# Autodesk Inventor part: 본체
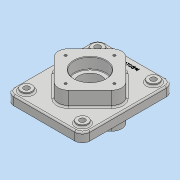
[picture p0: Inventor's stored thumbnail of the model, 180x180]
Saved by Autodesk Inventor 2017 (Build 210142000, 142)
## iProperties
Part Number: 본체
Material: 일반
Document SubType Name: Modeling
Designer: MRC
Density: 1 g/cm^3
Appearance: 기본값
Author: MRC
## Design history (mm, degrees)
sketch "스케치1"
  geometry: L1 (-75, -90)-(75, -90); L2 (75, -90)-(75, 90); L3 (75, 90)-(-75, 90); L4 (-75, 90)-(-75, -90); L5 (-75, -90)-(75, 90); L6 (75, -90)-(-75, 90); 1 further point
  constraints: 12 end point, 2 midpoint, 2 parallel, 1 horizontal, 1 perpendicular
  dimensions: "d0" = 150 distance of L2.end L3.end; "d1" = 180 distance of L3.end L1.start
extrude "돌출1" new body sketch "스케치1" distance "d2" = 18; taper "d3" = 0 deg
sketch "스케치2"
  geometry: L1 (0, -70.711)-(70.711, 0); L2 (70.711, 0)-(0, 70.711); L3 (0, 70.711)-(-70.711, 0); L4 (-70.711, 0)-(0, -70.711); L5 (0, -70.711)-(0, 70.711); L6 (70.711, 0)-(-70.711, 0); 1 further point
  constraints: 12 end point, 2 midpoint, 2 parallel, 1 horizontal, 1 perpendicular, 1 vertical
  dimensions: "d4" = 100 distance of L3.end L1.start
extrude "돌출2" join sketch "스케치2" distance "d5" = 29; taper "d6" = 0 deg
sketch "스케치3"
  geometry: L1 (0, -70.711)-(-70.711, 0) reference; L2 (-70.711, 0)-(0, 70.711) reference; L3 (0, 70.711)-(70.711, 0) reference; L4 (70.711, 0)-(0, -70.711) reference; 1 further point
extrude "돌출3" join sketch "스케치3" distance "d7" = 23; taper "d8" = 0 deg
fillet "모깎기1" dims "d9" = 15
sketch "스케치4"
  geometry: L1 (-75, 75)-(-75, -75) reference; L2 (-60, -90)-(60, -90) reference; L3 (75, -75)-(75, 75) reference; L4 (60, 90)-(-60, 90) reference; L5 (0, -70.711)-(-70.711, 0) reference; L6 (-70.711, 0)-(0, 70.711) reference; L7 (0, 70.711)-(70.711, 0) reference; L8 (70.711, 0)-(0, -70.711) reference; A1 r 15 centre (-60, 75) between (-60, 90) and (-75, 75) reference; A2 r 15 centre (-60, -75) between (-75, -75) and (-60, -90) reference; A3 r 15 centre (60, -75) between (60, -90) and (75, -75) reference; A4 r 15 centre (60, 75) between (75, 75) and (60, 90) reference; 2 further points
  constraints: 1 vertical alignment, 1 other
  dimensions: "d10" = 15 distance from line of L4 point (0, 75)
feature "엠보싱1" sketch "스케치4" dims "d0" = 150, "d1" = 180, "d11" = 0.5, "d12" = 0
fillet "모깎기2" dims "d13" = 20
sketch "스케치5"
  geometry: 1 further point
hole "구멍1" sketch "스케치5" at (0, 0) diameter "d14" = 45; stored, may be unused: countersink angle "d18" = 90 deg, drill point angle "d20" = 0 deg; dims "d15" = 6, "d16" = 62, "d17" = 22, "d19" = 100
sketch "스케치6"
  geometry: C1 r 31 at (0, 0); 1 further point
  constraints: 1 centre point, 1 coincident
  dimensions: "d21" = 62 diameter of C1
extrude "돌출4" cut sketch "스케치6" distance "d22" = 22; taper "d23" = 0 deg
sketch "스케치7"
  geometry: C1 r 11 at (-55, -70); 1 further point
  constraints: 1 centre point
  dimensions: "d24" = 22 diameter of C1; "d25" = 55 horizontal distance of point (0, 0) C1.centre; "d26" = 70 vertical distance of point (0, 0) C1.centre
extrude "돌출5" join sketch "스케치7" distance "d27" = 5; taper "d28" = 0 deg
sketch "스케치8"
  geometry: C1 r 5.5 at (0, 0); C2 r 11 at (0, 0) reference; 1 further point
  constraints: 1 centre point, 1 concentric
  dimensions: "d29" = 11 diameter of C1
extrude "돌출6" cut sketch "스케치8" stored distance "d30" = 5; taper "d31" = 0 deg
sketch "스케치9"
  geometry: 2 further points
  constraints: 1 vertical alignment
  dimensions: "d38" = 48 distance of point (0, 48) point (0, 0)
hole "구멍2" sketch "스케치9" at (0, 48) diameter "d39" = 4.917; stored, may be unused: countersink angle "d43" = 90 deg, drill point angle "d45" = 118 deg; dims "d40" = 10, "d41" = 62, "d42" = 22, "d44" = 13
node "작업 평면1"
fillet "모깎기3" dims "d49" = 3
fillet "모깎기4" dims "d50" = 1
chamfer "모따기1" distance "d51" = 1; stored, may be unused: second distance "d52" = 2, angle "d53" = 45 deg
node "솔리드1"
pattern_linear "직사각형 패턴1" dims "d34" = 110, "d37" = 140
pattern_circular "원형 패턴1" dims angle "d47" = 360 deg
mirror "미러1"
node "투영된 루프1"
node "투영된 루프2"
